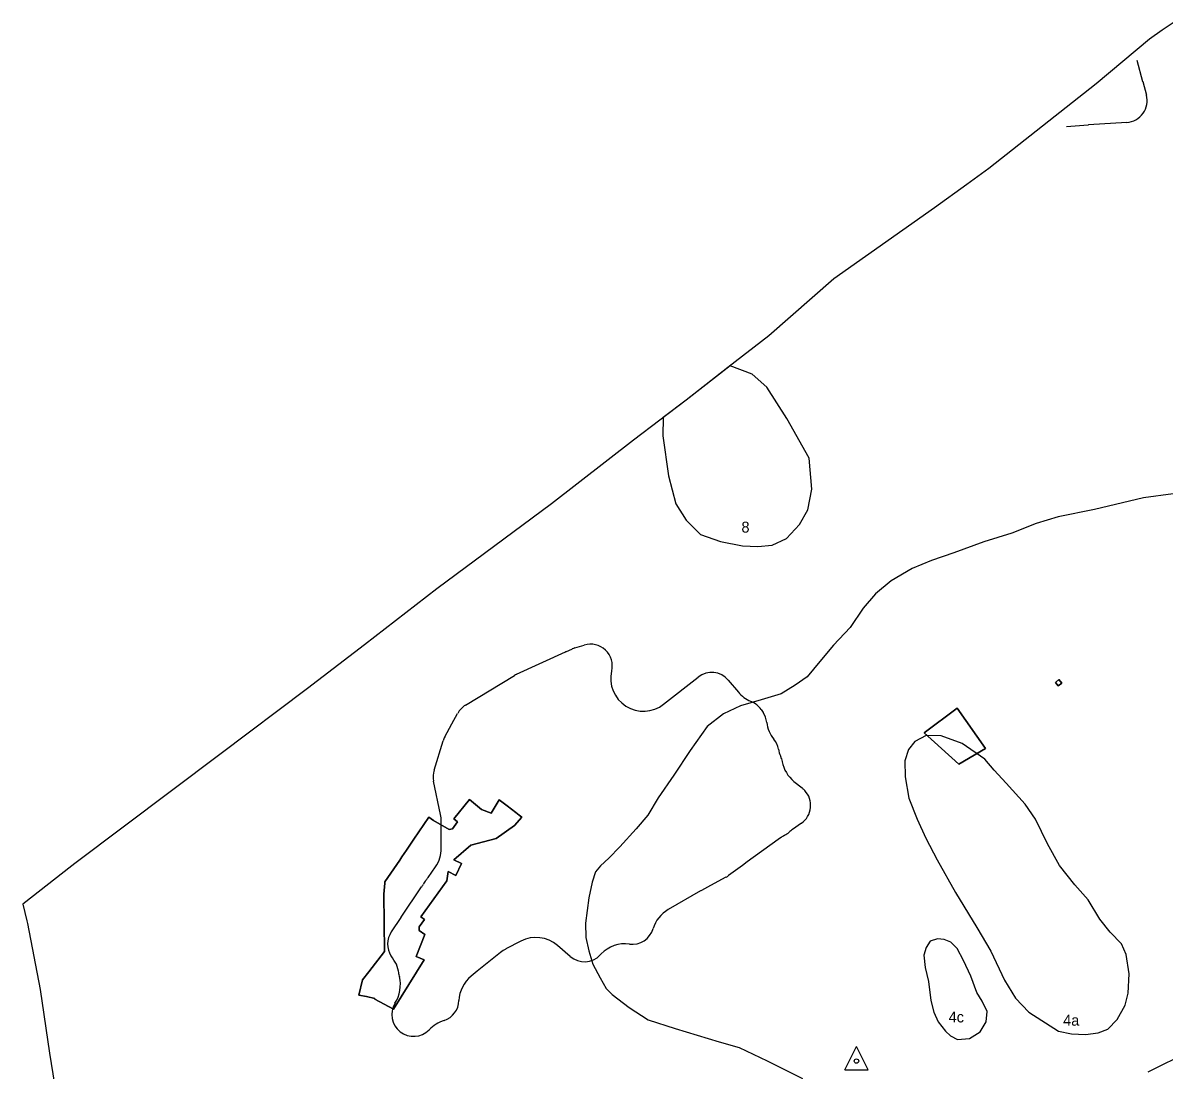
# Model space of a CAD drawing. Extents: x -445049 to -436194, y -1142460 to -1129816.
# Drawn here: x -444961 to -443912, y -1133134 to -1132171 of the extents above; entities that cross this region are included whole.
import ezdxf

# ---------------------------------------------------------------- set-up
doc = ezdxf.new("R2010")
doc.units = 0
for name, color, linetype in [('Vrstva 23', 7, 'Continuous'), ('Vrstva 51', 7, 'Continuous'), ('Vrstva 7', 7, 'Continuous')]:
    doc.layers.add(name, color=color, linetype=linetype)

msp = doc.modelspace()

# ---------------------------------------------------------------- linework, layer by layer
at = {"layer": 'Vrstva 23'}
for p, q in [((-443937, -1132205.2), (-443931.5, -1132224.7)), ((-443931.4, -1132224.9), (-443928.1, -1132237.2)), ((-443946, -1132262.3), (-443981.3, -1132264.7)), ((-443981.5, -1132264.8), (-444001.6, -1132266.3)), ((-444461.6, -1132749), (-444455.6, -1132746.3)), ((-444453.3, -1132745.5), (-444444.7, -1132742.9)), ((-444506.8, -1132769.7), (-444461.9, -1132749.1)), ((-444553.8, -1132798.1), (-444508.9, -1132770.8)), ((-444371.7, -1132797.1), (-444340, -1132772.2)), ((-444312.3, -1132775), (-444303, -1132786.2)), ((-444291.9, -1132794.5), (-444290.7, -1132795)), ((-444566.2, -1132815.2), (-444561, -1132805.6)), ((-444282.1, -1132802.1), (-444280.2, -1132804.9)), ((-444572.8, -1132827.2), (-444566.2, -1132815.2)), ((-444582.7, -1132857.7), (-444574.4, -1132830.9)), ((-444576.7, -1132898.6), (-444583.2, -1132867.8)), ((-444252, -1132868.1), (-444244.5, -1132874.1)), ((-444576, -1132929.5), (-444576, -1132904.8)), ((-444245.1, -1132906.6), (-444253.4, -1132912.4)), ((-444263.8, -1132919.7), (-444266.1, -1132921.3)), ((-444299.2, -1132945.4), (-444312, -1132954.7)), ((-444588.2, -1132956.6), (-444581.3, -1132946.7)), ((-444612.8, -1132992.9), (-444594.1, -1132965.2)), ((-444337.9, -1132968.8), (-444367.6, -1132986)), ((-444621.9, -1133006.5), (-444612.9, -1132993.2)), ((-444502.9, -1133015), (-444516.6, -1133022.2)), ((-444457.6, -1133029), (-444469.3, -1133018.9)), ((-444521.5, -1133025.4), (-444543, -1133042.7)), ((-444429.1, -1133026.7), (-444430, -1133027.7)), ((-444615.4, -1133042.7), (-444617.3, -1133036.2)), ((-444543, -1133042.7), (-444548.6, -1133047.2))]:
    msp.add_line(p, q, dxfattribs=at)
for points in [[(-444266.6, -1132921.6), (-444294.8, -1132942.2), (-444294.8, -1132942.2), (-444299.2, -1132945.4)], [(-444314.4, -1132956.2), (-444328.6, -1132963.9), (-444328.6, -1132963.9), (-444337, -1132968.3)]]:
    msp.add_lwpolyline(points, dxfattribs=at)
for centre, radius, start, end in [((-443950.7, -1132230.1), 20, 15.0742, 15.7871), ((-443947.4, -1132242.4), 20, 273.9182, 15.0742), ((-443979.3, -1132294.7), 30, 93.9182, 94.3055), ((-444447.5, -1132764.6), 20, 106.8085, 113.9602), ((-444438.9, -1132762), 20, 346.625, 106.8085), ((-444453.5, -1132767.3), 20, 113.9602, 114.6054), ((-444390.3, -1132773.6), 30, 166.625, 308.2914), ((-444498.5, -1132787.9), 20, 114.6054, 121.2481), ((-444327.6, -1132787.9), 20, 39.8977, 128.2914), ((-444280, -1132766.9), 30, 219.8977, 246.5472), ((-444543.4, -1132815.2), 20, 121.2481, 151.2958), ((-444298.7, -1132813.3), 20, 34.1172, 66.5472), ((-444296.8, -1132816.1), 20, 6.4846, 34.1172), ((-444548.7, -1132824.8), 20, 151.2958, 151.3058), ((-444247.1, -1132810.5), 30, 186.4846, 219.1068), ((-444555.3, -1132836.8), 20, 151.3058, 162.6926), ((-444285.9, -1132842), 20, 10.5055, 39.1068), ((-444236.8, -1132832.9), 30, 190.5055, 204.2455), ((-444282.3, -1132853.4), 20, 9.9891, 24.2455), ((-444233.1, -1132844.8), 30, 189.9891, 230.9978), ((-444563.6, -1132863.7), 20, 162.6926, 192.0067), ((-444256.6, -1132890.2), 20, 305.0129, 43.0707), ((-444257.1, -1132889.7), 20, 42.2656, 50.9978), ((-444220.1, -1132856.1), 30, 222.2656, 223.0707), ((-444606, -1132904.8), 30, 0.1084, 12.0067), ((-444236.2, -1132937), 30, 125.0129, 132.2803), ((-444248.9, -1132945.9), 30, 125.0445, 126.0853), ((-444246.6, -1132944.3), 30, 117.7269, 125.0445), ((-444269.9, -1132900), 20, 297.7269, 312.2803), ((-444606, -1132929.6), 30, 325.279, 0.1084), ((-444281.5, -1132969.6), 30, 126.0969, 126.1176), ((-444612.8, -1132939.5), 30, 319.3087, 325.279), ((-444323.8, -1132938.6), 20, 298.1153, 306.1176), ((-444618.9, -1132948.4), 30, 326.0254, 331.7403), ((-444574.9, -1132972.1), 20, 139.3087, 151.7403), ((-444322.9, -1132994.8), 30, 118.1266, 120.0822), ((-444352.6, -1133012), 30, 120.0822, 163.5298), ((-444637.8, -1132976.4), 30, 325.8892, 326.2789), ((-444596.4, -1133004.4), 20, 145.8892, 145.9145), ((-444596.2, -1133004.1), 20, 146.0254, 146.2789), ((-444605.4, -1133017.7), 20, 145.9145, 212.554), ((-444400.5, -1132997.8), 20, 262.1817, 343.5298), ((-444489, -1133041.6), 30, 49.1035, 117.6947), ((-444407.3, -1133047.4), 30, 82.1817, 136.6082), ((-446126.2, -1133988.6), 1784.3, 32.259, 32.554), ((-444502.7, -1133048.8), 30, 117.6947, 128.808), ((-444444.5, -1133013.9), 20, 229.1035, 316.6082), ((-444647.5, -1133054.4), 33.9, 328.5601, 11.5903), ((-444673.8, -1133057.9), 60.3, 10.2543, 14.5835), ((-444594.7, -1133043.6), 20, 190.2543, 191.5903), ((-444529.8, -1133070.6), 30, 128.8298, 178.1177), ((-444524.2, -1133066.1), 30, 128.808, 128.8298), ((-444579.8, -1133068.9), 20, 288.4869, 358.1177), ((-444601.5, -1133082.5), 20, 148.5601, 315.5193), ((-444562.4, -1133120.9), 34.8, 108.4869, 135.5193)]:
    msp.add_arc(centre, radius, start, end, dxfattribs=at)
at = {"layer": 'Vrstva 51'}
for p, q in [((-444205.2, -1133133.3), (-444194.5, -1133111.8)), ((-444183.7, -1133133.3), (-444194.5, -1133111.8)), ((-444205.2, -1133133.3), (-444183.7, -1133133.3))]:
    msp.add_line(p, q, dxfattribs=at)
for points in [[(-444372.2, -1132533.7), (-444372.5, -1132550.5), (-444367.2, -1132587.2), (-444360.5, -1132612.9), (-444351.1, -1132628), (-444337.7, -1132641.3), (-444319.3, -1132647.6), (-444299.1, -1132651.6), (-444285, -1132652.1), (-444271.9, -1132650.9), (-444258.7, -1132644.7), (-444246.9, -1132632), (-444239.2, -1132618.4), (-444235.6, -1132599.6), (-444237.9, -1132571.1), (-444258.4, -1132534.6), (-444276.8, -1132505.8), (-444290.3, -1132493.7), (-444310.6, -1132486), (-444351, -1132517.6)], [(-444140.8, -1132831.6), (-444146.7, -1132838.7), (-444150, -1132849.2), (-444149.8, -1132863.8), (-444146.3, -1132883.5), (-444138.7, -1132902.8), (-444130.9, -1132920.4), (-444120.3, -1132940.3), (-444103.5, -1132970.2), (-444083.9, -1133002.4), (-444071, -1133024.2), (-444058.4, -1133050.8), (-444048.5, -1133067.4), (-444036.2, -1133080.3), (-444008.8, -1133097.8), (-443997, -1133100.3), (-443984.1, -1133100.9), (-443972.4, -1133099.3), (-443963.4, -1133095.8), (-443954.9, -1133086.9), (-443947.6, -1133073.7), (-443944.7, -1133062.7), (-443943.8, -1133044.9), (-443946.6, -1133027.3), (-443950.9, -1133017.4), (-443961.3, -1133006.7), (-443970.8, -1132994.7), (-443981.5, -1132976.9), (-443993.7, -1132963.1), (-444007.8, -1132945.5), (-444019.1, -1132925.5), (-444029.9, -1132902.7), (-444039.6, -1132889.1), (-444056.9, -1132869.9), (-444068, -1132857.9), (-444076.4, -1132847.7), (-444097.3, -1132833.3), (-444116.7, -1132826.4), (-444130.4, -1132825.8)], [(-444126.8, -1133015), (-444130.5, -1133020.9), (-444132.7, -1133027.8), (-444131.5, -1133039.1), (-444128.3, -1133052.2), (-444126.3, -1133069.4), (-444123.4, -1133080.4), (-444119.4, -1133089), (-444112.6, -1133097.8), (-444108, -1133101.9), (-444101.6, -1133105.3), (-444090.7, -1133104.5), (-444080.7, -1133098.2), (-444075.4, -1133089), (-444074.3, -1133079.5), (-444079, -1133070.1), (-444083.8, -1133062.2), (-444089.3, -1133047.3), (-444096.1, -1133032.7), (-444101.9, -1133021.8), (-444107.7, -1133016), (-444113.8, -1133013.5), (-444120, -1133013)]]:
    msp.add_lwpolyline(points, close=True, dxfattribs=at)
for points in [[(-443903.6, -1132603.7), (-443930.8, -1132607.4), (-443975.7, -1132618.2), (-444009, -1132624.8), (-444029.4, -1132631.2), (-444051.6, -1132639.9), (-444077.6, -1132647.9), (-444104.9, -1132657.9), (-444125.4, -1132665.1), (-444143.3, -1132672.4), (-444162.5, -1132683.9), (-444177.1, -1132695.6), (-444188.4, -1132708.9), (-444200.2, -1132726.7), (-444215.5, -1132743), (-444228.2, -1132757.8), (-444239.7, -1132771.9), (-444250.7, -1132779.8), (-444263.7, -1132787.5), (-444282, -1132793.2), (-444301.1, -1132798.8), (-444316.6, -1132806), (-444331.6, -1132817.7), (-444347.3, -1132839.8), (-444362.3, -1132862.3), (-444376.8, -1132883.2), (-444386.3, -1132899.1), (-444396.8, -1132911.6), (-444412.1, -1132928.3), (-444422.1, -1132938.8), (-444429.6, -1132945.7), (-444434.2, -1132951.2), (-444437.4, -1132960.9), (-444440.6, -1132975.2), (-444443.6, -1132998.6), (-444443.3, -1133011.5), (-444440.5, -1133023.8), (-444436.8, -1133036.1), (-444429.9, -1133048.7), (-444424.4, -1133058.6), (-444419, -1133064), (-444403.3, -1133076), (-444385.9, -1133087.3), (-444361.2, -1133095.3), (-444320.6, -1133107.5), (-444302.3, -1133112.7), (-444276.6, -1133125), (-444244.2, -1133141.1)], [(-443926.5, -1133135.1), (-443888.1, -1133116)]]:
    msp.add_lwpolyline(points, dxfattribs=at)
msp.add_circle((-444194.5, -1133125.2), 2.03, dxfattribs=at)
at = {"layer": 'Vrstva 7'}
for points in [[(-443903.5, -1132170.8), (-443913.5, -1132177.7), (-443925.3, -1132185.7), (-443974.2, -1132227), (-444073, -1132304.7), (-444093.2, -1132319.4), (-444122.7, -1132340.9), (-444215.2, -1132406.2), (-444274.9, -1132458.5), (-444312.8, -1132487.8), (-444351, -1132517.6), (-444399.5, -1132554.4), (-444474.8, -1132613.1), (-444580.2, -1132691.1), (-444646.5, -1132742.7), (-444699.1, -1132782.7), (-444779.5, -1132843.3), (-444912.7, -1132943.6), (-444915.6, -1132945.8), (-444960.6, -1132981), (-444956.8, -1132996.2), (-444956.2, -1132998.8), (-444944.6, -1133059.3), (-444936.1, -1133117.9), (-444931.5, -1133146.3)], [(-443903.5, -1132170.8), (-443913.5, -1132177.7), (-443925.3, -1132185.7), (-443974.2, -1132227), (-444073, -1132304.7), (-444093.2, -1132319.4), (-444122.7, -1132340.9), (-444215.2, -1132406.2), (-444274.9, -1132458.5), (-444312.8, -1132487.8), (-444351, -1132517.6), (-444399.5, -1132554.4), (-444474.8, -1132613.1), (-444580.2, -1132691.1), (-444646.5, -1132742.7), (-444699.1, -1132782.7), (-444779.5, -1132843.3), (-444912.7, -1132943.6), (-444915.6, -1132945.8), (-444960.6, -1132981), (-444956.8, -1132996.2), (-444956.2, -1132998.8), (-444944.6, -1133059.3), (-444936.1, -1133117.9), (-444931.5, -1133146.3)], [(-443903.5, -1132170.8), (-443913.5, -1132177.7), (-443925.3, -1132185.7), (-443974.2, -1132227), (-444073, -1132304.7), (-444093.2, -1132319.4), (-444122.7, -1132340.9), (-444215.2, -1132406.2), (-444274.9, -1132458.5), (-444312.8, -1132487.8), (-444351, -1132517.6), (-444399.5, -1132554.4), (-444474.8, -1132613.1), (-444580.2, -1132691.1), (-444646.5, -1132742.7), (-444699.1, -1132782.7), (-444779.5, -1132843.3), (-444912.7, -1132943.6), (-444915.6, -1132945.8), (-444960.6, -1132981), (-444956.8, -1132996.2), (-444956.2, -1132998.8), (-444944.6, -1133059.3), (-444936.1, -1133117.9), (-444931.5, -1133146.3)], [(-444008.4, -1132774.6), (-444005.9, -1132777.8), (-444009, -1132780.3), (-444011.6, -1132777.1), (-444008.4, -1132774.6)], [(-444011.6, -1132777.1), (-444008.4, -1132774.6), (-444005.9, -1132777.8), (-444009, -1132780.3), (-444011.6, -1132777.1)], [(-444011.6, -1132777.1), (-444008.4, -1132774.6), (-444005.9, -1132777.8), (-444009, -1132780.3), (-444011.6, -1132777.1)], [(-444102, -1132800.7), (-444076, -1132837.8), (-444100.3, -1132852.3), (-444132.2, -1132823.6), (-444102, -1132800.7)], [(-444132.2, -1132823.6), (-444102, -1132800.7), (-444076, -1132837.8), (-444100.3, -1132852.3), (-444132.2, -1132823.6)], [(-444100.3, -1132852.3), (-444132.2, -1132823.6), (-444102, -1132800.7), (-444076, -1132837.8), (-444100.3, -1132852.3)], [(-444132.2, -1132823.6), (-444102, -1132800.7), (-444076, -1132837.8), (-444100.3, -1132852.3), (-444132.2, -1132823.6)], [(-444501.9, -1132901.1), (-444508.9, -1132908.8), (-444525.5, -1132920.7), (-444549, -1132926.9), (-444564.6, -1132940.2), (-444557.4, -1132943.7), (-444562.6, -1132954.5), (-444569.8, -1132951.1), (-444570.8, -1132959.6), (-444594.7, -1132992.6), (-444591.4, -1132995), (-444596.4, -1133001.9), (-444596.5, -1133005.2), (-444591.3, -1133009), (-444599.1, -1133029.1), (-444591.8, -1133032.2), (-444620.1, -1133077.4), (-444637.2, -1133068.4), (-444637, -1133067.7), (-444644.8, -1133065.9), (-444651.9, -1133064.5), (-444648.3, -1133050.6), (-444642.6, -1133043.2), (-444628.2, -1133024.4), (-444628.8, -1132971.7), (-444628, -1132961.7), (-444628, -1132960.5), (-444614.2, -1132940.4), (-444612.3, -1132937.6), (-444608, -1132931.2), (-444601.2, -1132921.2), (-444587.6, -1132901.1), (-444583.2, -1132904), (-444568.8, -1132912.3), (-444565.7, -1132911.6), (-444561, -1132905.4), (-444564.5, -1132902.4), (-444550.2, -1132884.8), (-444539.2, -1132894), (-444530.3, -1132897.2), (-444522.7, -1132885), (-444515.6, -1132890.5), (-444507.5, -1132896.8), (-444504.6, -1132899.1), (-444501.9, -1132901.1)], [(-444504.6, -1132899.1), (-444501.9, -1132901.1), (-444508.9, -1132908.8), (-444525.5, -1132920.7), (-444549, -1132926.9), (-444564.6, -1132940.2), (-444557.4, -1132943.7), (-444562.6, -1132954.5), (-444569.8, -1132951.1), (-444570.8, -1132959.6), (-444594.7, -1132992.6), (-444591.4, -1132995), (-444596.4, -1133001.9), (-444596.5, -1133005.2), (-444591.3, -1133009), (-444599.1, -1133029.1), (-444591.8, -1133032.2), (-444620.1, -1133077.4), (-444637.2, -1133068.4), (-444637, -1133067.7), (-444644.8, -1133065.9), (-444651.9, -1133064.5), (-444648.3, -1133050.6), (-444642.6, -1133043.2), (-444628.2, -1133024.4), (-444628.8, -1132971.7), (-444628, -1132961.7), (-444628, -1132960.5), (-444614.2, -1132940.4), (-444612.3, -1132937.6), (-444608, -1132931.2), (-444601.2, -1132921.2), (-444587.6, -1132901.1), (-444583.2, -1132904), (-444568.8, -1132912.3), (-444565.7, -1132911.6), (-444561, -1132905.4), (-444564.5, -1132902.4), (-444550.2, -1132884.8), (-444539.2, -1132894), (-444530.3, -1132897.2), (-444522.7, -1132885), (-444515.6, -1132890.5), (-444507.5, -1132896.8), (-444504.6, -1132899.1)], [(-444507.5, -1132896.8), (-444504.6, -1132899.1), (-444501.9, -1132901.1), (-444508.9, -1132908.8), (-444525.5, -1132920.7), (-444549, -1132926.9), (-444564.6, -1132940.2), (-444557.4, -1132943.7), (-444562.6, -1132954.5), (-444569.8, -1132951.1), (-444570.8, -1132959.6), (-444594.7, -1132992.6), (-444591.4, -1132995), (-444596.4, -1133001.9), (-444596.5, -1133005.2), (-444591.3, -1133009), (-444599.1, -1133029.1), (-444591.8, -1133032.2), (-444620.1, -1133077.4), (-444637.2, -1133068.4), (-444637, -1133067.7), (-444644.8, -1133065.9), (-444651.9, -1133064.5), (-444648.3, -1133050.6), (-444642.6, -1133043.2), (-444628.2, -1133024.4), (-444628.8, -1132971.7), (-444628, -1132961.7), (-444628, -1132960.5), (-444614.2, -1132940.4), (-444612.3, -1132937.6), (-444608, -1132931.2), (-444601.2, -1132921.2), (-444587.6, -1132901.1), (-444583.2, -1132904), (-444568.8, -1132912.3), (-444565.7, -1132911.6), (-444561, -1132905.4), (-444564.5, -1132902.4), (-444550.2, -1132884.8), (-444539.2, -1132894), (-444530.3, -1132897.2), (-444522.7, -1132885), (-444515.6, -1132890.5), (-444507.5, -1132896.8)], [(-444601.2, -1132921.2), (-444587.6, -1132901.1), (-444583.2, -1132904), (-444568.8, -1132912.3), (-444565.7, -1132911.6), (-444561, -1132905.4), (-444564.5, -1132902.4), (-444550.2, -1132884.8), (-444539.2, -1132894), (-444530.3, -1132897.2), (-444522.7, -1132885), (-444515.6, -1132890.5), (-444507.5, -1132896.8), (-444504.6, -1132899.1), (-444501.9, -1132901.1), (-444508.9, -1132908.8), (-444525.5, -1132920.7), (-444549, -1132926.9), (-444564.6, -1132940.2), (-444557.4, -1132943.7), (-444562.6, -1132954.5), (-444569.8, -1132951.1), (-444570.8, -1132959.6), (-444594.7, -1132992.6), (-444591.4, -1132995), (-444596.4, -1133001.9), (-444596.5, -1133005.2), (-444591.3, -1133009), (-444599.1, -1133029.1), (-444591.8, -1133032.2), (-444620.1, -1133077.4), (-444637.2, -1133068.4), (-444637, -1133067.7), (-444644.8, -1133065.9), (-444651.9, -1133064.5), (-444648.3, -1133050.6), (-444642.6, -1133043.2), (-444628.2, -1133024.4), (-444628.8, -1132971.7), (-444628, -1132961.7), (-444628, -1132960.5), (-444614.2, -1132940.4), (-444612.3, -1132937.6), (-444608, -1132931.2), (-444601.2, -1132921.2)]]:
    msp.add_lwpolyline(points, dxfattribs=at)
for points in [[(-444008.4, -1132774.6), (-444011.6, -1132777.1), (-444009, -1132780.3), (-444005.9, -1132777.8)], [(-444102, -1132800.7), (-444132.2, -1132823.6), (-444100.3, -1132852.3), (-444076, -1132837.8)], [(-444501.9, -1132901.1), (-444504.6, -1132899.1), (-444507.5, -1132896.8), (-444515.6, -1132890.5), (-444522.7, -1132885), (-444530.3, -1132897.2), (-444539.2, -1132894), (-444550.2, -1132884.8), (-444564.5, -1132902.4), (-444561, -1132905.4), (-444565.7, -1132911.6), (-444568.8, -1132912.3), (-444583.2, -1132904), (-444587.6, -1132901.1), (-444601.2, -1132921.2), (-444608, -1132931.2), (-444612.3, -1132937.6), (-444614.2, -1132940.4), (-444628, -1132960.5), (-444628, -1132961.7), (-444628.8, -1132971.7), (-444628.2, -1133024.4), (-444642.6, -1133043.2), (-444648.3, -1133050.6), (-444651.9, -1133064.5), (-444644.8, -1133065.9), (-444637, -1133067.7), (-444637.2, -1133068.4), (-444620.1, -1133077.4), (-444591.8, -1133032.2), (-444599.1, -1133029.1), (-444591.3, -1133009), (-444596.5, -1133005.2), (-444596.4, -1133001.9), (-444591.4, -1132995), (-444594.7, -1132992.6), (-444570.8, -1132959.6), (-444569.8, -1132951.1), (-444562.6, -1132954.5), (-444557.4, -1132943.7), (-444564.6, -1132940.2), (-444549, -1132926.9), (-444525.5, -1132920.7), (-444508.9, -1132908.8)]]:
    msp.add_lwpolyline(points, close=True, dxfattribs=at)

# ---------------------------------------------------------------- texts
at = {"layer": 'Vrstva 51'}
for s, p in [('8', (-444300.2, -1132639.4)), ('4c', (-444109.8, -1133089.7)), ('4a', (-444004.6, -1133092.7))]:
    msp.add_text(s, height=10, dxfattribs=at).set_placement(p)

doc.saveas('drawing.dxf')
